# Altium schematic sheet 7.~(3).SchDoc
size 420 x 297 mm
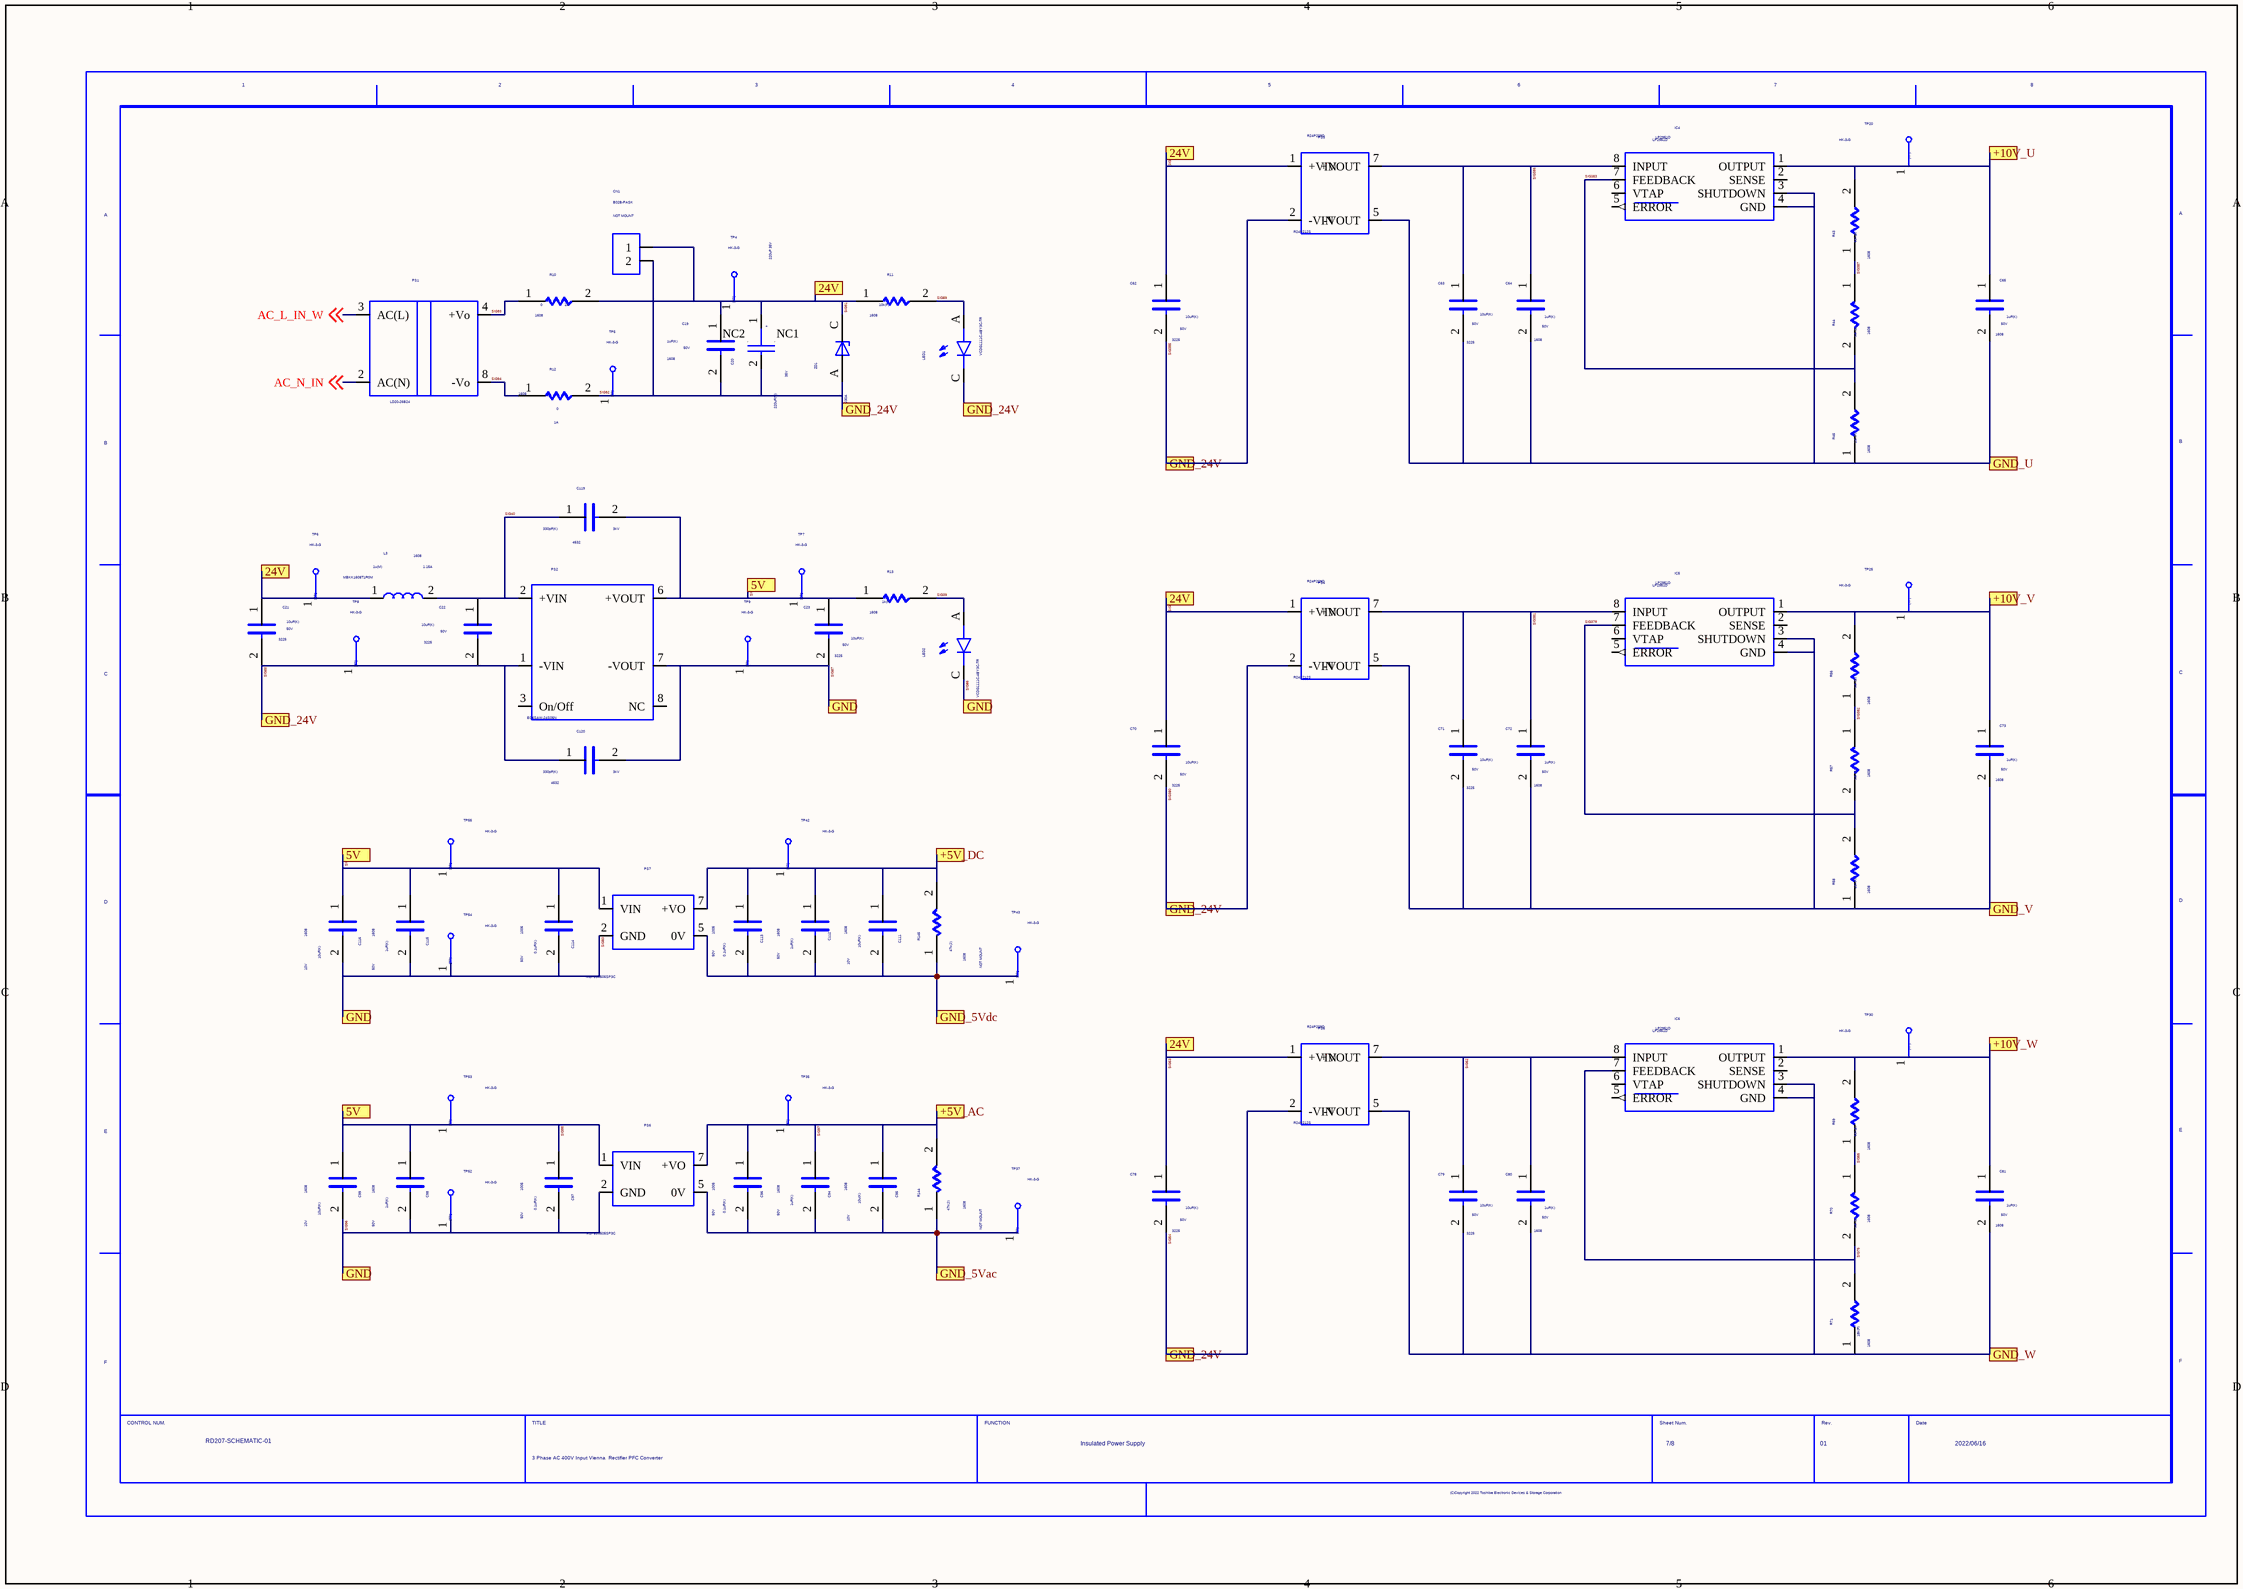
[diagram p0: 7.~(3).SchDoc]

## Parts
C19  SIZECODESMD: 1608  VAL2: 50V  VAL1: 1uF(K)  (hidden comment: C)
C20  NOTE: 220uF 35V  VAL2: 35V  VAL1: 220uF(M)  (hidden comment: MAL216099001E3)
C21  SIZECODESMD: 3225  VAL2: 50V  VAL1: 10uF(K)  (hidden comment: C)
C22  SIZECODESMD: 3225  VAL2: 50V  VAL1: 10uF(K)  (hidden comment: C)
C23  SIZECODESMD: 3225  VAL2: 50V  VAL1: 10uF(K)  (hidden comment: C)
C62  SIZECODESMD: 3225  VAL2: 50V  VAL1: 10uF(K)  (hidden comment: C)
C63  SIZECODESMD: 3225  VAL2: 50V  VAL1: 10uF(K)  (hidden comment: C)
C64  SIZECODESMD: 1608  VAL2: 50V  VAL1: 1uF(K)  (hidden comment: C)
C65  SIZECODESMD: 1608  VAL2: 50V  VAL1: 1uF(K)  (hidden comment: C)
C70  SIZECODESMD: 3225  VAL2: 50V  VAL1: 10uF(K)  (hidden comment: C)
C71  SIZECODESMD: 3225  VAL2: 50V  VAL1: 10uF(K)  (hidden comment: C)
C72  SIZECODESMD: 1608  VAL2: 50V  VAL1: 1uF(K)  (hidden comment: C)
C73  SIZECODESMD: 1608  VAL2: 50V  VAL1: 1uF(K)  (hidden comment: C)
C78  SIZECODESMD: 3225  VAL2: 50V  VAL1: 10uF(K)  (hidden comment: C)
C79  SIZECODESMD: 3225  VAL2: 50V  VAL1: 10uF(K)  (hidden comment: C)
C80  SIZECODESMD: 1608  VAL2: 50V  VAL1: 1uF(K)  (hidden comment: C)
C81  SIZECODESMD: 1608  VAL2: 50V  VAL1: 1uF(K)  (hidden comment: C)
C94  SIZECODESMD: 1608  VAL2: 50V  VAL1: 1uF(K)  (hidden comment: C)
C95  SIZECODESMD: 1608  VAL2: 10V  VAL1: 10u(K)  (hidden comment: C)
C96  SIZECODESMD: 1005  VAL2: 50V  VAL1: 0.1uF(K)  (hidden comment: C)
C97  SIZECODESMD: 1005  VAL2: 50V  VAL1: 0.1uF(K)  (hidden comment: C)
C98  SIZECODESMD: 1608  VAL2: 50V  VAL1: 1uF(K)  (hidden comment: C)
C99  SIZECODESMD: 1608  VAL2: 10V  VAL1: 10uF(K)  (hidden comment: C)
C111  SIZECODESMD: 1608  VAL2: 10V  VAL1: 10uF(K)  (hidden comment: C)
C112  SIZECODESMD: 1608  VAL2: 50V  VAL1: 1uF(K)  (hidden comment: C)
C113  SIZECODESMD: 1005  VAL2: 50V  VAL1: 0.1uF(K)  (hidden comment: C)
C114  SIZECODESMD: 1005  VAL2: 50V  VAL1: 0.1uF(K)  (hidden comment: C)
C115  SIZECODESMD: 1608  VAL2: 50V  VAL1: 1uF(K)  (hidden comment: C)
C116  SIZECODESMD: 1608  VAL2: 10V  VAL1: 10uF(K)  (hidden comment: C)
C119  SIZECODESMD: 4532  VAL2: 3kV  VAL1: 330pF(K)  (hidden comment: C)
C120  SIZECODESMD: 4532  VAL2: 3kV  VAL1: 330pF(K)  (hidden comment: C)
CN1  NOTMOUNT: NOT MOUNT  (hidden comment: BM02B-PASS-1-TFT(LF)(SN))
IC4  LP2951D
IC5  LP2951D
IC6  LP2951D
L3  SIZECODESMD: 1608  VAL3: MBKK1608T1R0M  VAL2: 1.15A  VAL1: 1u(M)  (hidden comment: L)
LED1  VCDG1111C-4BY3C-TR
LED2  VCDG1111C-4BY3C-TR
PS1  LD20-26B24
PS2  EC5SAW-24S05N
PS3  R24P209D
PS4  R24P209D
PS5  R24P209D
PS6  MEF1S0505SP3C
PS7  MEF1S0505SP3C
R10  SIZECODESMD: 1608  VAL2: 1A  VAL1: 0  (hidden comment: R)
R11  SIZECODESMD: 1608  VAL1: 10k(F)  (hidden comment: R)
R12  SIZECODESMD: 1608  VAL2: 1A  VAL1: 0  (hidden comment: R)
R13  SIZECODESMD: 1608  VAL1: 1k(F)  (hidden comment: R)
R43  SIZECODESMD: 1608  VAL1: 68k(B)  (hidden comment: R)
R44  SIZECODESMD: 1608  VAL1: 68k(B)  (hidden comment: R)
R45  SIZECODESMD: 1608  VAL1: 18k(F)  (hidden comment: R)
R56  SIZECODESMD: 1608  VAL1: 68k(B)  (hidden comment: R)
R57  SIZECODESMD: 1608  VAL1: 68k(B)  (hidden comment: R)
R58  SIZECODESMD: 1608  VAL1: 18k(F)  (hidden comment: R)
R69  SIZECODESMD: 1608  VAL1: 68k(B)  (hidden comment: R)
R70  SIZECODESMD: 1608  VAL1: 68k(B)  (hidden comment: R)
R71  SIZECODESMD: 1608  VAL1: 18k(F)  (hidden comment: R)
R144  NOTMOUNT: NOT MOUNT  SIZECODESMD: 1608  VAL1: 47k(J)  (hidden comment: R)
R145  NOTMOUNT: NOT MOUNT  SIZECODESMD: 1608  VAL1: 47k(J)  (hidden comment: R)
TP4  VAL3: HK-3-G  (hidden comment: TP)
TP5  VAL3: HK-3-G  (hidden comment: TP)
TP6  VAL3: HK-3-G  (hidden comment: TP)
TP7  VAL3: HK-3-G  (hidden comment: TP)
TP8  VAL3: HK-3-G  (hidden comment: TP)
TP9  VAL3: HK-3-G  (hidden comment: TP)
TP20  VAL3: HK-3-G  (hidden comment: TP)
TP25  VAL3: HK-3-G  (hidden comment: TP)
TP30  VAL3: HK-3-G  (hidden comment: TP)
TP35  VAL3: HK-3-G  (hidden comment: TP)
TP37  VAL3: HK-3-G  (hidden comment: TP)
TP42  VAL3: HK-3-G  (hidden comment: TP)
TP43  VAL3: HK-3-G  (hidden comment: TP)
TP52  VAL3: HK-3-G  (hidden comment: TP)
TP53  VAL3: HK-3-G  (hidden comment: TP)
TP54  VAL3: HK-3-G  (hidden comment: TP)
TP55  VAL3: HK-3-G  (hidden comment: TP)
U?  DATE: 2022/06/16  TITLE: 3 Phase AC 400V Input Vienna / Rectifier PFC Converter  REVISION: 01  SHEETNUMBER: 7/8  FUNCTION: Insulated Power Supply  DRAWINGNUMBER: RD207-SCHEMATIC-01  (hidden comment: WAKU_DEF100)
ZD1  VAL3: SMBJ30A  (hidden comment: ZD)

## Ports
5V, 24V, +5V_AC, +5V_DC, +10V_U, +10V_V, +10V_W, GND, GND_5Vac, GND_5Vdc, GND_24V, GND_U, GND_V, GND_W

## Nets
+5V_DC: C111.1 C112.1 C113.1 PS7.7(+VO) R145.2 TP42.1 ; port +5V_DC
+10V_U: C65.1 IC4.1(OUTPUT) R43.2 TP20.1 ; port +10V_U
+10V_V: C73.1 IC5.1(OUTPUT) R56.2 TP25.1 ; port +10V_V
+10V_W: C81.1 IC6.1(OUTPUT) R69.2 TP30.1 ; port +10V_W
AC_L_IN_W: PS1.3(AC(L)) ; off-sheet AC_L_IN_W
AC_N_IN: PS1.2(AC(N)) ; off-sheet AC_N_IN
GND_5Vac: C94.2 C95.2 C96.2 PS6.5(0V) R144.1 TP37.1 ; port GND_5Vac
GND_5Vdc: C111.2 C112.2 C113.2 PS7.5(0V) R145.1 TP43.1 ; port GND_5Vdc
GND_U: C63.2 C64.2 C65.2 IC4.3(SHUTDOWN) IC4.4(GND) PS3.5(-VOUT) R45.1 ; port GND_U
GND_V: C71.2 C72.2 C73.2 IC5.3(SHUTDOWN) IC5.4(GND) PS4.5(-VOUT) R58.1 ; port GND_V
GND_W: C79.2 C80.2 C81.2 IC6.3(SHUTDOWN) IC6.4(GND) PS5.5(-VOUT) R71.1 ; port GND_W
SIG39: LED2.A R13.2
SIG40: C22.1 C119.1 L3.2 PS2.2(+VIN)
SIG47: C23.1 C97.1 C98.1 C99.1 C114.1 C115.1 C116.1 C119.2 PS2.6(+VOUT) PS6.1(VIN) PS7.1(VIN) R13.1 TP7.1 TP53.1 TP55.1 ; port 5V  [also labelled SIG81, SIG95]
SIG52: C79.1 C80.1 IC6.8(INPUT) PS5.7(+VOUT)
SIG55: R69.1 R70.1
SIG75: IC6.7(FEEDBACK) R70.2 R71.2
SIG83: C23.2 C97.2 C98.2 C99.2 C114.2 C115.2 C116.2 C120.2 LED2.C PS2.7(-VOUT) PS6.2(GND) PS7.2(GND) TP9.1 TP52.1 TP54.1 ; port GND  [also labelled SIG86, SIG87, SIG96]
SIG89: LED1.A R11.2
SIG93: PS1.4(+Vo) R10.1
SIG94: PS1.8(-Vo) R12.1
SIG97: C94.1 C95.1 C96.1 PS6.7(+VO) R144.2 TP35.1 ; port +5V_AC
SIG378: IC5.7(FEEDBACK) R57.2 R58.2
SIG379: C19.1 C20.1 C21.1 C62.1 C70.1 C78.1 CN1.1 L3.1 PS3.1(+VIN) PS4.1(+VIN) PS5.1(+VIN) R10.2 R11.1 TP4.1 TP6.1 ZD1.C ; port 24V  [also labelled SIG384, SIG53, SIG91]
SIG380: C19.2 C20.2 C21.2 C22.2 C62.2 C70.2 C78.2 C120.1 CN1.2 LED1.C PS2.1(-VIN) PS3.2(-VIN) PS4.2(-VIN) PS5.2(-VIN) R12.2 TP5.1 TP8.1 ZD1.A ; port GND_24V  [also labelled SIG385, SIG54, SIG88, SIG92]
SIG381: C71.1 C72.1 IC5.8(INPUT) PS4.7(+VOUT)
SIG382: R56.1 R57.1
SIG383: IC4.7(FEEDBACK) R44.2 R45.2
SIG386: C63.1 C64.1 IC4.8(INPUT) PS3.7(+VOUT)
SIG387: R43.1 R44.1

Not connected (* = marked no-connect by the designer): C20 NC1 NC2; IC4 2(SENSE) 5(ERROR) 6(VTAP); IC5 2(SENSE) 5(ERROR) 6(VTAP); IC6 2(SENSE) 5(ERROR) 6(VTAP); PS2 3(On/Off) 8(NC)

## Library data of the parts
C19 C64 C65 C72 C73 C80 C81 C94 C98 C112 C115 = C: OriginalSymbolOrigin: (2540,7620); COMP: -C-UMK107AB7105KA-T
C20 = MAL216099001E3: Aluminum,35V,±20%; MANUFACTURER: Vishay; COMP: -C-MAL216099001E3; TIME: 11:39:41; UPDATEUSER: t5459927; UPDATETIME: 17:02:27; SAVECOUNT: 2; SAVEAREA0: -15593,-10586,20389,5809; OriginalSymbolOrigin: (0,0)
C21-C23 C62 C63 C70 C71 C78 C79 = C: OriginalSymbolOrigin: (2540,7620); COMP: -C-UMK325AB7106KM-T
C95 C99 C111 C116 = C: OriginalSymbolOrigin: (2540,7620); COMP: -C-GRM188D71A106KA73D
C96 C97 C113 C114 = C: OriginalSymbolOrigin: (2540,7620); COMP: -C-UMK105BJ104KV-F
C119 C120 = C: OriginalSymbolOrigin: (2540,7620); COMP: -C-C4532CH3F331K250KA
CN1 = B02B-PASK: Connector, 250V, 3A; MANUFACTURER: JST; COMP: -CN-NC_B02B-PASK; NOTE: 2pin; TIME: 11:39:42; UPDATEUSER: t5459927; UPDATETIME: 16:50:18; SAVECOUNT: 6; SAVEAREA0: -5711,-10440,12954,3224; OriginalSymbolOrigin: (0,0)
IC4-IC6 = LP2951D: Voltage Regulators; MANUFACTURER: Txsas Instruments; COMP: -IC-LP2951D; TIME: 16:53:55; UPDATEUSER: t5459927; UPDATETIME: 16:15:29; SAVECOUNT: 3; SAVEAREA0: -15946,-25147,36340,13186; OriginalSymbolOrigin: (0,0)
L3 = L: OriginalSymbolOrigin: (2540,5080); COMP: -L-MBKK1608T1R0M
LED1 LED2 = VCDG1111C_4BY3C_TR: LED; MANUFACTURER: STANLEY; COMP: -LED-VCDG1111C-4BY3C-TR_AC; NOTE: Green; TIME: 11:39:41; UPDATEUSER: t5459927; SAVECOUNT: 1; OriginalSymbolOrigin: (0,-2540); SIZECODESMD: 1608; INSTANCENAME: INS17056102
PS1 = LD20_26B24: AC/DC Converter; MANUFACTURER: Mornsun; COMP: PS-LD20-26B24; TIME: 11:39:42; UPDATEUSER: t5459927; UPDATETIME: 17:04:57; SAVECOUNT: 2; SAVEAREA0: -3533,-18371,23278,1256; OriginalSymbolOrigin: (0,0)
PS2 = EC5SAW_24S05N: DC/DC Converter; MANUFACTURER: CINCON; COMP: PS-EC5SAW-24S05N; TIME: 11:39:40; UPDATEUSER: t5459927; UPDATETIME: 14:27:04; SAVECOUNT: 4; SAVEAREA0: -8840,-26929,31144,2341; OriginalSymbolOrigin: (0,0)
PS3-PS5 = R24P212S: DC/DC Converter; MANUFACTURER: RECOM; COMP: -PS-R24P212S; TIME: 16:53:55; UPDATEUSER: t5459927; UPDATETIME: 16:30:09; SAVECOUNT: 6; SAVEAREA0: -9940,-15240,22833,0; OriginalSymbolOrigin: (0,0)
PS6 PS7 = MEF1S0505SP3C: DC/DC Converter; MANUFACTURER: MORNSUN; COMP: PS-MEF1S0505SP3C; TIME: 16:53:55; UPDATEUSER: t5459927; UPDATETIME: 13:45:31; SAVECOUNT: 4; SAVEAREA0: -2499,-12525,17820,2350; OriginalSymbolOrigin: (0,0)
R10 R12 = R: OriginalSymbolOrigin: (5080,5080); COMP: -R-RK73Z1JTTD
R11 = R: OriginalSymbolOrigin: (5080,5080); VAL2: 100mW; COMP: -R-ERJ3EKF1002V
R13 = R: OriginalSymbolOrigin: (5080,5080); VAL2: 125mW; COMP: -R-RK73H1JTTD1001F
R43 R44 R56 R57 R69 R70 = R: OriginalSymbolOrigin: (5080,5080); VAL2: 100mW; COMP: -R-ERJ3EKF6802V
R45 R58 R71 = R: OriginalSymbolOrigin: (5080,5080); VAL2: 100mW; COMP: -R-ERJ3EKF1802V
R144 R145 = R: OriginalSymbolOrigin: (5080,5080); COMP: -R-NC_R1608; VAL2: 100mW
TP4-TP9 TP20 TP25 TP30 TP35 TP37 TP42 TP43 TP52-TP55 = TP: TIME: 16:12:21; UPDATEUSER: fukuda-y; UPDATETIME: 16:18:11; SAVECOUNT: 2; SAVEAREA0: -242,-92,12810,7836; OriginalSymbolOrigin: (0,7620); COMP: -TP-HK-3-G
U? = WAKU_DEF100: PLOTTIME: HH:MM; SAVEAREA0: 22200,72372,612276,319236; TIME: 14:30:25; UPDATEUSER: t5459927; UPDATETIME: 09:21:33; SAVECOUNT: 7; OriginalSymbolOrigin: (10160,284480)
ZD1 = ZD: SAVEAREA0: -4630,-153,17114,13055; TIME: 14:49:55; UPDATEUSER: fukuda-y; UPDATETIME: 08:18:42; SAVECOUNT: 6; OriginalSymbolOrigin: (5080,5080); COMP: -ZD-SMBJ30A_AC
